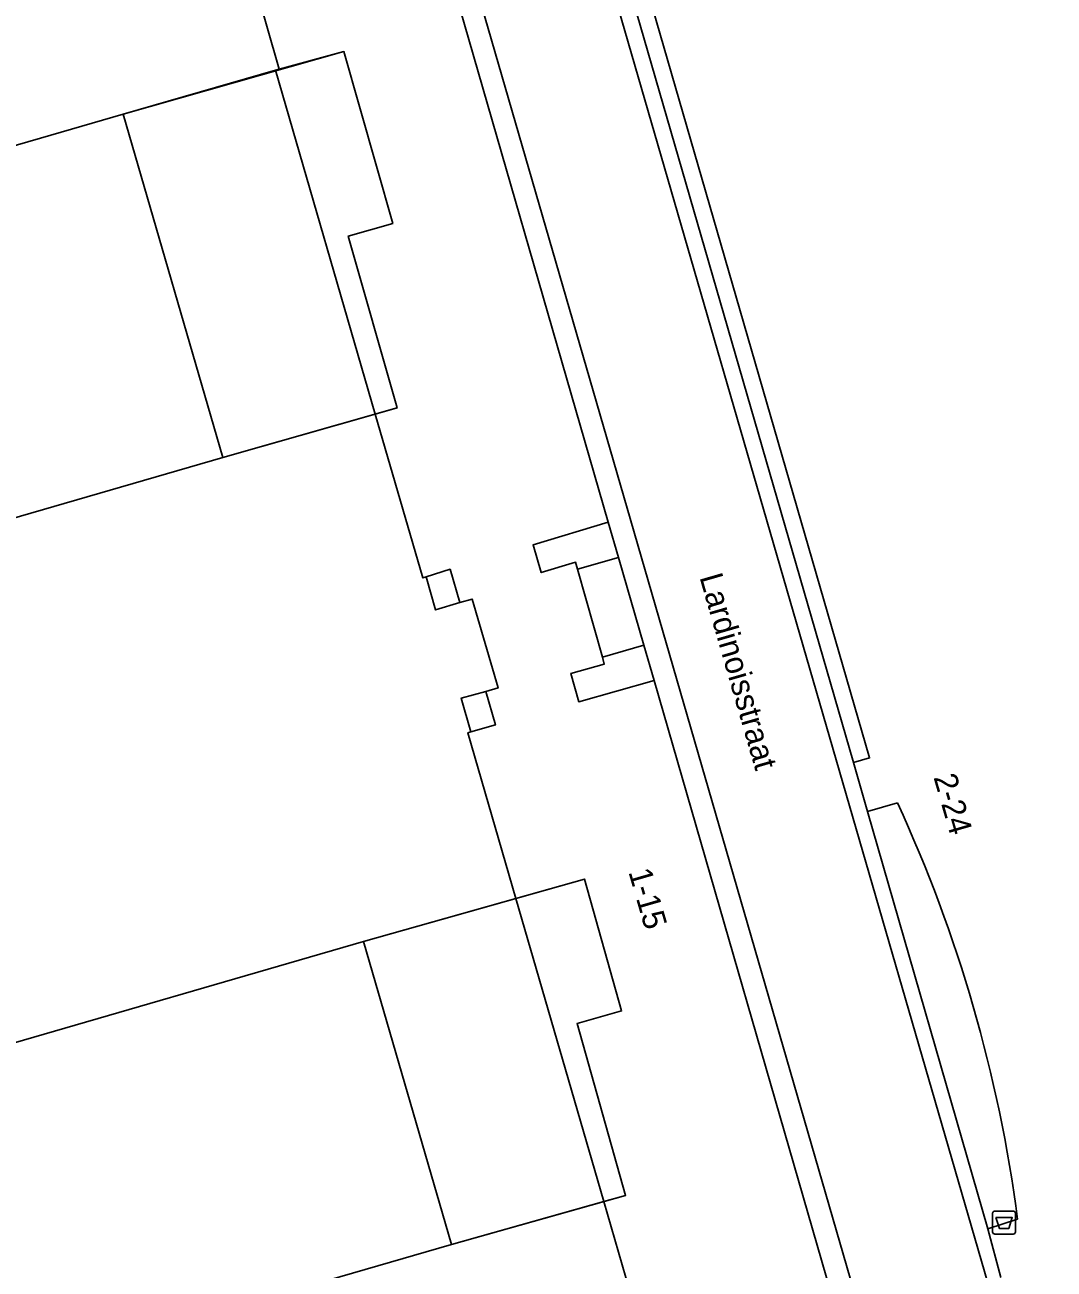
# Model space of a CAD drawing. Extents: x 160806 to 161707, y 383697 to 384148.
# Drawn here: x 161130.1 to 161174.6, y 383760.5 to 383814.4 of the extents above; entities that cross this region are included whole.
import ezdxf

# ---------------------------------------------------------------- set-up
doc = ezdxf.new("R2010")
doc.units = 0
for name, color, linetype in [('IMGEO_Afvalbak', 7, 'Continuous'), ('IMGEO_Muur', 7, 'Continuous'), ('IMGEO_Openbare_ruimte_label', 7, 'Continuous'), ('IMGEO_Pand', 7, 'Continuous'), ('IMGEO_Pand_nummerreeks', 7, 'Continuous'), ('IMGEO_Pand_overbouw', 7, 'Continuous'), ('IMGEO_Rijbaan_lokaal_gesloten', 7, 'Continuous'), ('IMGEO_Voetgangersgebied_open', 7, 'Continuous'), ('IMGEO_Voetpad_op_trap', 7, 'Continuous')]:
    doc.layers.add(name, color=color, linetype=linetype)

msp = doc.modelspace()

# ---------------------------------------------------------------- linework, layer by layer
at = {"layer": 'IMGEO_Afvalbak'}
for p, q in [((161171.984, 383762.134), (161171.984, 383762.934)), ((161171.984, 383762.934), (161171.984, 383762.134)), ((161172.084, 383763.034), (161172.874, 383763.034)), ((161172.874, 383763.034), (161172.084, 383763.034)), ((161172.974, 383762.934), (161172.974, 383762.134)), ((161172.974, 383762.134), (161172.974, 383762.934)), ((161172.874, 383762.034), (161172.084, 383762.034)), ((161172.084, 383762.034), (161172.874, 383762.034))]:
    msp.add_line(p, q, dxfattribs=at)
msp.add_lwpolyline([(161172.127, 383762.748), (161172.831, 383762.748), (161172.682, 383762.278), (161172.276, 383762.278), (161172.127, 383762.748)], dxfattribs=at)
for centre, start, end in [((161172.084, 383762.934), 90, 180), ((161172.084, 383762.934), 90, 180), ((161172.874, 383762.934), 0, 90), ((161172.874, 383762.934), 360, 90), ((161172.084, 383762.134), 180, 270), ((161172.084, 383762.134), 180, 270), ((161172.874, 383762.134), 270, 0), ((161172.874, 383762.134), 270, 0)]:
    msp.add_arc(centre, 0.1, start, end, dxfattribs=at)
at = {"layer": 'IMGEO_Muur'}
for points in [[(161155.337, 383792.863), (161155.777, 383791.339)], [(161155.777, 383791.339), (161154.006, 383790.835)], [(161148.91, 383789.383), (161147.854, 383789.064), (161147.448, 383790.495)], [(161155.087, 383787.012), (161156.886, 383787.54)], [(161156.886, 383787.54), (161157.328, 383786.009)], [(161149.393, 383783.784), (161148.975, 383785.247), (161150.034, 383785.528)]]:
    msp.add_lwpolyline(points, dxfattribs=at)
at = {"layer": 'IMGEO_Pand'}
for points in [[(161140.029, 383820.121), (161140.091, 383819.928), (161140.148, 383819.75), (161140.63, 383819.901), (161141.522, 383816.764), (161139.994, 383816.318), (161141.082, 383812.479)], [(161155.337, 383792.863), (161147.904, 383818.638)], [(161155.737, 383817.796), (161156.438, 383818.002), (161166.655, 383782.656), (161165.953, 383782.453)], [(161141.082, 383812.479), (161143.896, 383813.245), (161146.008, 383805.802), (161144.083, 383805.255), (161146.194, 383797.813), (161145.248, 383797.544)], [(161134.336, 383810.532), (161119.356, 383806.193)], [(161138.655, 383795.672), (161134.336, 383810.532)], [(161145.248, 383797.544), (161147.304, 383790.45), (161147.448, 383790.495)], [(161104.037, 383785.627), (161138.655, 383795.672)], [(161154.006, 383790.835), (161153.924, 383791.126), (161152.441, 383790.682), (161152.081, 383791.89), (161155.337, 383792.863)], [(161147.448, 383790.495), (161148.491, 383790.823), (161148.91, 383789.383)], [(161155.087, 383787.012), (161154.006, 383790.835)], [(161148.91, 383789.383), (161149.449, 383789.537), (161150.572, 383785.685), (161150.034, 383785.528)], [(161157.328, 383786.009), (161154.058, 383785.089), (161153.714, 383786.313), (161155.169, 383786.721), (161155.087, 383787.012)], [(161165.188, 383758.759), (161157.328, 383786.009)], [(161150.034, 383785.528), (161150.456, 383784.084), (161149.393, 383783.784)], [(161149.393, 383783.784), (161149.261, 383783.747), (161151.34, 383776.574)], [(161165.953, 383782.453), (161166.564, 383780.339)], [(161166.564, 383780.339), (161167.861, 383780.714)], [(161151.34, 383776.574), (161154.306, 383777.411), (161155.919, 383771.696), (161153.991, 383771.151), (161156.091, 383763.71), (161155.146, 383763.443)], [(161144.737, 383774.709), (161111.5, 383765.061), (161112.655, 383761.086), (161111.258, 383760.68)], [(161148.546, 383761.579), (161144.737, 383774.709)], [(161155.146, 383763.443), (161157.212, 383756.317)], [(161173.066, 383762.677), (161171.77, 383762.265)], [(161171.77, 383762.265), (161172.335, 383760.149)], [(161113.902, 383751.548), (161148.546, 383761.579)]]:
    msp.add_lwpolyline(points, dxfattribs=at)
msp.add_arc((161110.965, 383754.526), 62.634, 7.47771, 24.71576, dxfattribs=at)
at = {"layer": 'IMGEO_Pand_overbouw'}
for points in [[(161155.737, 383817.796), (161165.953, 383782.453), (161166.655, 383782.656), (161156.438, 383818.002)], [(161134.336, 383810.532), (161138.655, 383795.672), (161146.194, 383797.813), (161144.083, 383805.255), (161146.008, 383805.802), (161143.896, 383813.245)], [(161144.737, 383774.709), (161148.546, 383761.579), (161156.091, 383763.71), (161153.991, 383771.151), (161155.919, 383771.696), (161154.306, 383777.411)]]:
    msp.add_lwpolyline(points, close=True, dxfattribs=at)
for points in [[(161167.861, 383780.714), (161166.564, 383780.339)], [(161166.564, 383780.339), (161171.77, 383762.265), (161173.066, 383762.677)]]:
    msp.add_lwpolyline(points, dxfattribs=at)
msp.add_arc((161110.965, 383754.526), 62.634, 7.47771, 24.71576, dxfattribs=at)
at = {"layer": 'IMGEO_Rijbaan_lokaal_gesloten'}
for points in [[(161140.931, 383812.437), (161134.336, 383810.532)], [(161140.931, 383812.437), (161145.248, 383797.544)], [(161138.655, 383795.672), (161145.248, 383797.544)], [(161144.737, 383774.709), (161151.34, 383776.574)], [(161151.34, 383776.574), (161155.146, 383763.443)], [(161148.546, 383761.579), (161155.146, 383763.443)]]:
    msp.add_lwpolyline(points, dxfattribs=at)
at = {"layer": 'IMGEO_Voetgangersgebied_open'}
for points in [[(161153.492, 383823.019), (161174.649, 383750), (161178.009, 383738.404)], [(161173.934, 383732.031), (161172.636, 383736.558), (161168.744, 383750), (161156.16, 383793.469), (161148.092, 383821.328)], [(161155.737, 383817.796), (161165.953, 383782.453)], [(161166.564, 383780.339), (161171.77, 383762.265)]]:
    msp.add_lwpolyline(points, dxfattribs=at)
at = {"layer": 'IMGEO_Voetpad_op_trap'}
for points in [[(161141.082, 383812.479), (161140.931, 383812.437)], [(161156.886, 383787.54), (161155.777, 383791.339)]]:
    msp.add_lwpolyline(points, dxfattribs=at)

# ---------------------------------------------------------------- texts
at = {"layer": 'IMGEO_Openbare_ruimte_label'}
msp.add_text('Lardinoisstraat', height=1, rotation=286.1342, dxfattribs=at).set_placement((161159.285, 383790.488))
at = {"layer": 'IMGEO_Pand_nummerreeks'}
for s, rotation, p in [('2-24', 286.1228, (161169.418, 383781.821)), ('1-15', 286.1443, (161156.206, 383777.724))]:
    msp.add_text(s, height=1, rotation=rotation, dxfattribs=at).set_placement(p)

doc.saveas('drawing.dxf')
